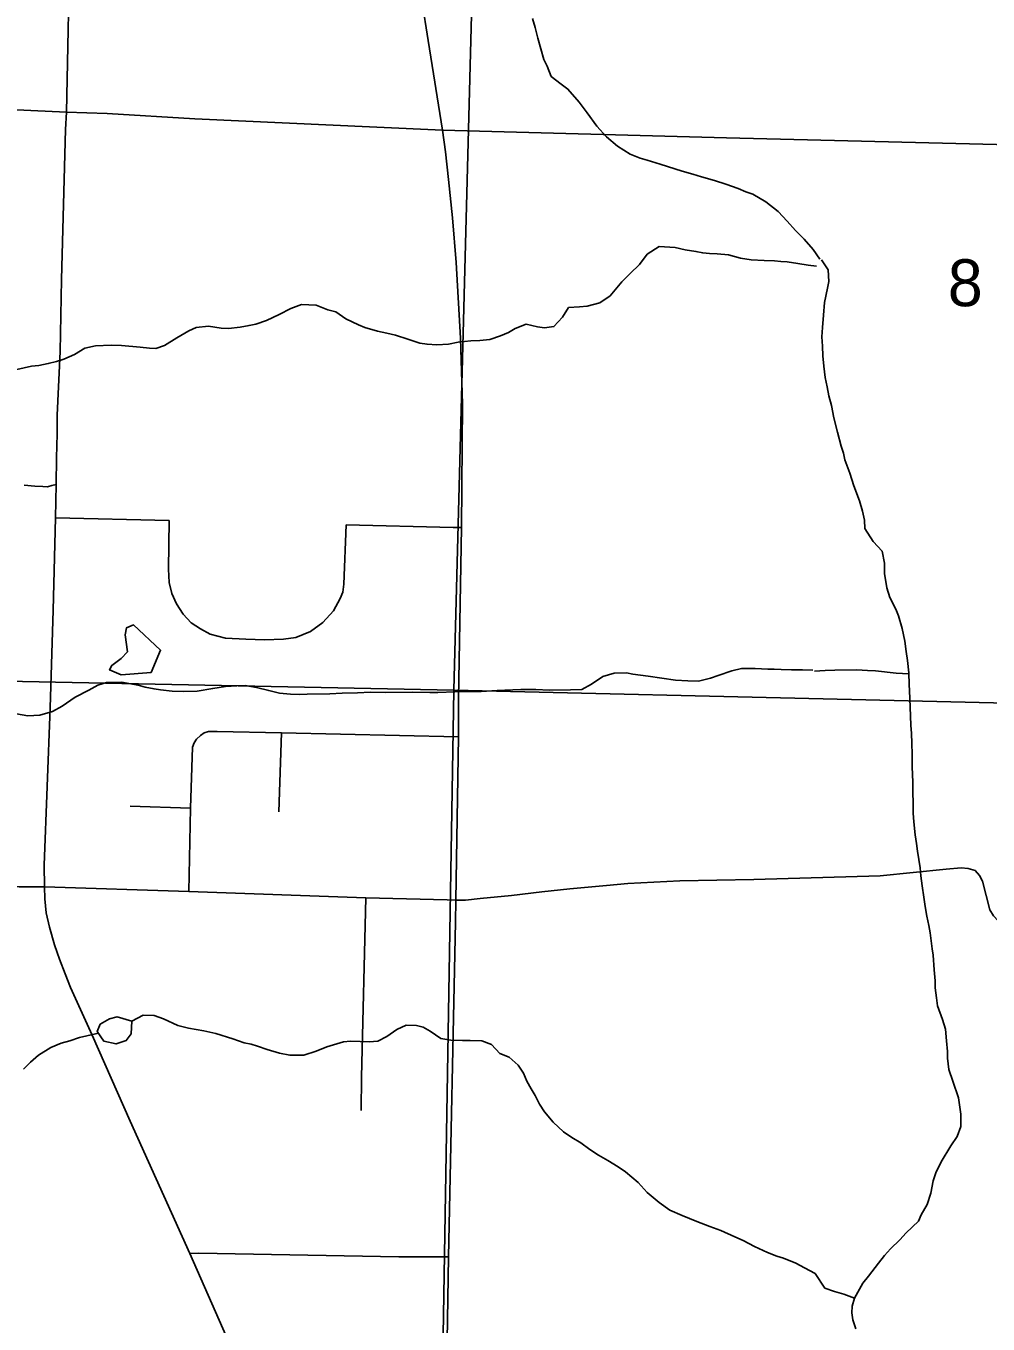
# Model space of a CAD drawing. Extents: x 0 to 34, y -5 to 22.
# Drawn here: x 6.617 to 7.476, y 14.888 to 16.047 of the extents above; entities that cross this region are included whole.
import ezdxf

# ---------------------------------------------------------------- set-up
doc = ezdxf.new("R2010")
doc.units = 0
for name, color, linetype in [('GM_X_County_Road', 7, 'Continuous'), ('GM_X_Minor_Lake', 7, 'Continuous'), ('GM_X_Minor_River', 7, 'Continuous'), ('GM_X_Section', 7, 'Continuous'), ('GM_X_Section_Text', 7, 'Continuous'), ('GM_X_Township_Road', 7, 'Continuous')]:
    doc.layers.add(name, color=color, linetype=linetype)

msp = doc.modelspace()

# ---------------------------------------------------------------- linework, layer by layer
at = {"layer": 'GM_X_County_Road'}
for points in [[(6.6334, 15.2782), (6.6332, 15.2975), (6.6383, 15.4381), (6.641, 15.5253), (6.6432, 15.6078), (6.6438, 15.6374), (6.644, 15.6612), (6.6448, 15.6826), (6.6448, 15.6993), (6.6473, 15.7562), (6.6485, 15.8206), (6.652, 15.9546), (6.653, 15.9701), (6.6564, 16.1323), (6.6579, 16.1853), (6.6591, 16.2211), (6.6597, 16.2456), (6.6595, 16.2668), (6.6587, 16.2825), (6.6569, 16.2955), (6.6542, 16.3151)], [(6.9889, 15.9539), (6.9761, 16.034), (6.9703, 16.0698), (6.9579, 16.1328), (6.9396, 16.2097), (6.9381, 16.2154)], [(6.1391, 15.9958), (6.2017, 15.9925), (6.4743, 15.9785), (6.653, 15.9701), (6.6892, 15.9687), (6.7675, 15.9642), (6.9301, 15.9567), (6.9889, 15.9539)], [(7.0004, 15.2464), (7.0008, 15.2663), (7.003, 15.4122), (7.0032, 15.4463), (7.0057, 15.5991), (7.0066, 15.7091), (7.0048, 15.7682), (7.0012, 15.8358), (6.9979, 15.8756), (6.9943, 15.91), (6.9914, 15.9345), (6.9889, 15.9539)], [(6.9889, 15.9539), (7.2426, 15.947), (7.5439, 15.9397)], [(6.8057, 14.8538), (6.7632, 14.9507), (6.71, 15.0687), (6.6758, 15.1457), (6.6566, 15.1883), (6.6518, 15.2005), (6.6469, 15.2134), (6.6446, 15.2195), (6.6422, 15.2264), (6.6379, 15.2421), (6.6348, 15.2549), (6.6338, 15.2674), (6.6334, 15.2782)], [(6.987, 14.4985), (6.9943, 14.9477), (7.0004, 15.2464)]]:
    msp.add_lwpolyline(points, dxfattribs=at)
at = {"layer": 'GM_X_Minor_Lake'}
for points in [[(6.7286, 15.4696), (6.7371, 15.4894), (6.713, 15.512), (6.7066, 15.5093), (6.7055, 15.5032), (6.7075, 15.4881), (6.7019, 15.4819), (6.6936, 15.4758), (6.6914, 15.472), (6.7019, 15.4673)], [(6.7019, 15.4673), (6.7286, 15.4696)], [(6.7115, 15.158), (6.6982, 15.162), (6.6914, 15.1601), (6.6831, 15.1554), (6.6805, 15.149), (6.6863, 15.1403), (6.6973, 15.1377), (6.7064, 15.1408), (6.7109, 15.1469)], [(6.7109, 15.1469), (6.7115, 15.158)]]:
    msp.add_lwpolyline(points, dxfattribs=at)
at = {"layer": 'GM_X_Minor_River'}
for points in [[(7.0693, 16.0538), (7.0716, 16.0455), (7.074, 16.036), (7.0795, 16.017), (7.0822, 16.011), (7.086, 16.0019), (7.0948, 15.9951), (7.1009, 15.9906), (7.1109, 15.9789), (7.1182, 15.9695), (7.1266, 15.9574), (7.1354, 15.948), (7.1453, 15.9397), (7.1564, 15.9326), (7.1655, 15.9289), (7.1716, 15.927), (7.1834, 15.9237), (7.2028, 15.9174), (7.2123, 15.9145), (7.2203, 15.9123), (7.2317, 15.9089), (7.242, 15.9056), (7.253, 15.9019)], [(7.253, 15.9019), (7.2598, 15.8989), (7.2659, 15.8967), (7.2777, 15.89), (7.2888, 15.8813), (7.2968, 15.8727), (7.3041, 15.8644), (7.3118, 15.8565), (7.3198, 15.8474), (7.3259, 15.8387)], [(7.0312, 15.767), (7.0407, 15.7702), (7.0478, 15.7733), (7.0539, 15.7767), (7.0637, 15.7806), (7.0736, 15.7784), (7.08, 15.7773), (7.0884, 15.7785), (7.0959, 15.787), (7.1015, 15.7954), (7.1113, 15.7962), (7.1182, 15.7967), (7.1295, 15.7998), (7.1385, 15.8059), (7.1491, 15.8186), (7.1566, 15.8259), (7.1648, 15.8339), (7.1716, 15.8431), (7.1825, 15.85), (7.1966, 15.849), (7.2057, 15.8472), (7.2152, 15.8457), (7.2213, 15.8443), (7.2273, 15.8439), (7.2341, 15.8436), (7.2444, 15.8426), (7.255, 15.8396), (7.2645, 15.8382), (7.2763, 15.8375), (7.2854, 15.8372), (7.2911, 15.8365), (7.2968, 15.8362), (7.3063, 15.8347), (7.3154, 15.8333), (7.323, 15.8326)], [(7.3274, 15.8382), (7.3332, 15.8292), (7.334, 15.8189), (7.3326, 15.8128), (7.3301, 15.7999), (7.329, 15.7888), (7.3284, 15.7778), (7.3277, 15.7694), (7.3282, 15.7611), (7.3286, 15.7524), (7.3295, 15.7432), (7.3307, 15.733), (7.3323, 15.7247), (7.3339, 15.7167), (7.3363, 15.708), (7.3383, 15.697), (7.3418, 15.6841), (7.345, 15.6716), (7.3469, 15.6655), (7.3481, 15.6595), (7.3528, 15.6477), (7.3563, 15.6364), (7.3614, 15.6228), (7.3641, 15.6137), (7.3657, 15.6057), (7.3662, 15.5981), (7.3735, 15.5864), (7.3815, 15.5778), (7.3835, 15.5671), (7.3836, 15.558), (7.3857, 15.5451), (7.3884, 15.5364), (7.3938, 15.5262), (7.3961, 15.5202), (7.3993, 15.5088), (7.4017, 15.4974), (7.4029, 15.4883), (7.4041, 15.4803), (7.4054, 15.4693), (7.4058, 15.4587), (7.4059, 15.453), (7.4063, 15.4462), (7.4069, 15.4306), (7.4073, 15.4226), (7.4078, 15.415), (7.4079, 15.4063), (7.4083, 15.3964), (7.4084, 15.3854), (7.409, 15.3717), (7.4092, 15.344), (7.4097, 15.336), (7.4109, 15.3246), (7.4121, 15.3167), (7.413, 15.3098), (7.4154, 15.295), (7.4162, 15.2878), (7.4174, 15.2791), (7.4187, 15.2688), (7.4199, 15.2605), (7.4215, 15.2518), (7.4231, 15.2434), (7.4243, 15.237), (7.4263, 15.2226), (7.4272, 15.2169), (7.428, 15.204), (7.4289, 15.1941), (7.429, 15.188), (7.4302, 15.1789), (7.431, 15.1717), (7.4353, 15.1596), (7.438, 15.1509), (7.4389, 15.1406), (7.4398, 15.1311), (7.4398, 15.1251), (7.441, 15.1148), (7.4446, 15.1046), (7.4496, 15.0895), (7.4517, 15.075), (7.4518, 15.064), (7.4485, 15.0552), (7.4428, 15.0468), (7.4343, 15.0323), (7.4294, 15.0227), (7.4272, 15.0155), (7.425, 15.0045), (7.4217, 14.9942), (7.4165, 14.985), (7.4139, 14.9793), (7.403, 14.9689), (7.3974, 14.9627), (7.3891, 14.9547), (7.3835, 14.9489), (7.3782, 14.942), (7.3692, 14.9302), (7.3643, 14.924), (7.3569, 14.9106), (7.3547, 14.9034), (7.3544, 14.8977), (7.3552, 14.8912), (7.3579, 14.8833)], [(6.6087, 15.7402), (6.6219, 15.743), (6.6284, 15.7438), (6.6367, 15.7454), (6.6442, 15.7474), (6.6507, 15.7493), (6.6601, 15.7536), (6.6695, 15.7593), (6.679, 15.7613), (6.693, 15.7618), (6.7021, 15.7615), (6.7188, 15.7602), (6.7272, 15.7591), (6.7329, 15.7588), (6.7404, 15.7615), (6.7517, 15.7684), (6.7623, 15.7746), (6.7687, 15.7777), (6.7797, 15.7789), (6.7911, 15.7771), (6.7976, 15.7768), (6.8082, 15.778), (6.8161, 15.7796), (6.8222, 15.7808), (6.8316, 15.7839), (6.8429, 15.7893), (6.8535, 15.7947), (6.863, 15.7982), (6.8759, 15.7976), (6.8865, 15.7935), (6.8937, 15.7917), (6.9025, 15.7853), (6.9139, 15.7801), (6.9196, 15.7778), (6.9307, 15.7745), (6.939, 15.7727), (6.947, 15.7709), (6.958, 15.7672), (6.9687, 15.7638), (6.9751, 15.7627), (6.9838, 15.7621), (6.9941, 15.7629), (7.0028, 15.7645), (7.0141, 15.7657), (7.0221, 15.7662), (7.0312, 15.767)], [(6.6083, 15.4325), (6.6186, 15.4307), (6.6292, 15.4315), (6.6405, 15.4347), (6.6492, 15.4393), (6.6609, 15.4474), (6.673, 15.4536), (6.6809, 15.4582), (6.6888, 15.4605), (6.7021, 15.461), (6.7169, 15.4581), (6.7234, 15.4563), (6.7313, 15.4548), (6.737, 15.4541), (6.7473, 15.4527), (6.7579, 15.4524), (6.7697, 15.4529), (6.7837, 15.4553), (6.795, 15.4569), (6.8053, 15.4577), (6.8125, 15.4578), (6.8227, 15.456), (6.8337, 15.4534), (6.8432, 15.4512), (6.8531, 15.4502), (6.8607, 15.4499), (6.8679, 15.4503), (6.8883, 15.4505), (6.8993, 15.451), (6.913, 15.4515), (6.9244, 15.4519), (6.9376, 15.4517), (6.9619, 15.4519), (6.9774, 15.4516), (6.9846, 15.4517), (6.9998, 15.4522), (7.0233, 15.4524), (7.0377, 15.4533), (7.0445, 15.4537), (7.0589, 15.4542), (7.0722, 15.4544), (7.0843, 15.4537), (7.1033, 15.4539), (7.1132, 15.4543), (7.1218, 15.459), (7.132, 15.4659), (7.1422, 15.469), (7.1532, 15.4691), (7.1589, 15.468), (7.1726, 15.4662), (7.1969, 15.4627), (7.2079, 15.462), (7.2174, 15.4617), (7.2283, 15.4644), (7.2351, 15.4668), (7.2472, 15.4711), (7.2559, 15.473), (7.2681, 15.4731), (7.2795, 15.4725), (7.2851, 15.4725), (7.2912, 15.4722), (7.3007, 15.4719), (7.3105, 15.472), (7.3197, 15.4717)], [(7.4054, 15.4684), (7.394, 15.4688), (7.3757, 15.4709), (7.3685, 15.4712), (7.359, 15.4719), (7.3393, 15.4717), (7.3306, 15.4712), (7.3211, 15.4707)], [(6.7115, 15.158), (6.7214, 15.1634), (6.7312, 15.1631), (6.7396, 15.1601), (6.7525, 15.1541), (6.762, 15.1519), (6.7757, 15.1494), (6.7863, 15.1472), (6.8015, 15.1424), (6.8118, 15.1387), (6.8179, 15.1376), (6.8236, 15.1358), (6.8323, 15.1328), (6.8434, 15.1295), (6.8525, 15.1277), (6.8589, 15.1277), (6.865, 15.1278), (6.876, 15.1313), (6.8854, 15.1352), (6.9005, 15.1395), (6.9066, 15.1403), (6.9153, 15.14), (6.9233, 15.1397), (6.9312, 15.1401), (6.9392, 15.1444), (6.9482, 15.1505), (6.9565, 15.1544), (6.9656, 15.1541), (6.9717, 15.1526), (6.9778, 15.1492), (6.9873, 15.1425), (6.9964, 15.141), (7.0067, 15.1408), (7.0135, 15.1408), (7.0241, 15.1405), (7.0325, 15.1372), (7.0402, 15.1293), (7.0485, 15.1259), (7.0565, 15.1188), (7.0612, 15.1116), (7.0643, 15.1044), (7.0681, 15.0976), (7.0716, 15.0916), (7.0754, 15.084), (7.08, 15.0772), (7.0877, 15.0678), (7.0969, 15.0591), (7.1045, 15.0542), (7.1125, 15.0494), (7.1205, 15.0434), (7.1281, 15.0385), (7.1365, 15.0336), (7.1457, 15.028), (7.1522, 15.0235), (7.1636, 15.0141), (7.1717, 15.005), (7.1824, 14.996), (7.1919, 14.9893), (7.2029, 14.9844), (7.2159, 14.9792), (7.2277, 14.9748), (7.2375, 14.971), (7.2501, 14.9655), (7.2573, 14.9621), (7.2676, 14.9569), (7.279, 14.9516), (7.2874, 14.9483), (7.2935, 14.9465), (7.3045, 14.942), (7.3122, 14.9379), (7.3217, 14.9326), (7.3302, 14.9195)], [(6.6145, 15.1153), (6.6209, 15.1215), (6.628, 15.1276), (6.639, 15.1345), (6.6484, 15.1384), (6.656, 15.1404), (6.6647, 15.1435), (6.6816, 15.1473)], [(7.3569, 14.9106), (7.3474, 14.9143), (7.339, 14.9165), (7.3302, 14.9195)]]:
    msp.add_lwpolyline(points, dxfattribs=at)
at = {"layer": 'GM_X_Section'}
for points in [[(7.0252, 16.4555), (8.0868, 16.4255), (8.0646, 15.4287), (6.9989, 15.4538)], [(6.139, 15.4711), (6.9989, 15.4538), (6.9822, 14.4457), (6.1471, 14.4654), (6.1461, 14.6292)], [(8.0646, 15.4287), (8.041, 14.419), (6.9822, 14.4457), (6.9989, 15.4538)]]:
    msp.add_lwpolyline(points, close=True, dxfattribs=at)
at = {"layer": 'GM_X_Township_Road'}
for p, q in [((6.6432, 15.6078), (6.7447, 15.6052)), ((6.8427, 15.3452), (6.8451, 15.4157)), ((6.71, 15.3501), (6.7638, 15.3483))]:
    msp.add_line(p, q, dxfattribs=at)
for points in [[(6.6153, 15.6368), (6.6247, 15.636), (6.6318, 15.6356), (6.6359, 15.6355), (6.64, 15.6365), (6.6438, 15.6374)], [(6.7447, 15.6052), (6.7441, 15.5618), (6.7447, 15.5498), (6.7471, 15.54), (6.7514, 15.5308), (6.7573, 15.5216), (6.7644, 15.5139), (6.7728, 15.5084), (6.7813, 15.5039), (6.795, 15.5003), (6.8133, 15.4994), (6.83, 15.4988), (6.8468, 15.4994), (6.858, 15.5009), (6.871, 15.5062), (6.882, 15.5143), (6.8914, 15.5245), (6.8975, 15.5357), (6.8997, 15.5414), (6.9007, 15.5483), (6.9028, 15.6015)], [(6.9028, 15.6015), (6.9985, 15.5991), (7.0057, 15.5991)], [(6.7624, 15.2739), (6.7638, 15.3483), (6.7657, 15.4029), (6.7671, 15.4067), (6.7691, 15.41), (6.7726, 15.4132), (6.776, 15.4155), (6.7799, 15.4169), (6.7875, 15.4169), (6.8451, 15.4157), (7.003, 15.4122)], [(6.1441, 15.3068), (6.3871, 15.2902), (6.5104, 15.281), (6.5794, 15.2786), (6.6106, 15.2782), (6.6334, 15.2782), (6.7624, 15.2739), (6.9205, 15.2682), (6.9931, 15.2665), (7.0008, 15.2663)], [(7.0008, 15.2663), (7.0094, 15.2661), (7.0224, 15.2676), (7.0505, 15.2702), (7.0776, 15.2737), (7.1025, 15.2763), (7.1353, 15.2792), (7.1543, 15.281), (7.2007, 15.2835), (7.267, 15.2845), (7.3797, 15.2879), (7.4387, 15.2938), (7.4521, 15.2949), (7.4584, 15.2943), (7.4645, 15.2926), (7.4686, 15.2883), (7.4713, 15.2831), (7.4778, 15.2576), (7.481, 15.2521), (7.4851, 15.2476), (7.4918, 15.2439), (7.4973, 15.2439), (7.5037, 15.2466), (7.535, 15.2621)], [(6.9162, 15.0783), (6.9166, 15.1082), (6.9205, 15.2682)], [(6.7632, 14.9507), (6.7712, 14.9509), (6.9499, 14.9475), (6.9943, 14.9477)]]:
    msp.add_lwpolyline(points, dxfattribs=at)

# ---------------------------------------------------------------- texts
at = {"layer": 'GM_X_Section_Text'}
msp.add_text('8', height=0.0419, rotation=0, dxfattribs=at).set_placement((7.4402, 15.7967))

doc.saveas('drawing.dxf')
